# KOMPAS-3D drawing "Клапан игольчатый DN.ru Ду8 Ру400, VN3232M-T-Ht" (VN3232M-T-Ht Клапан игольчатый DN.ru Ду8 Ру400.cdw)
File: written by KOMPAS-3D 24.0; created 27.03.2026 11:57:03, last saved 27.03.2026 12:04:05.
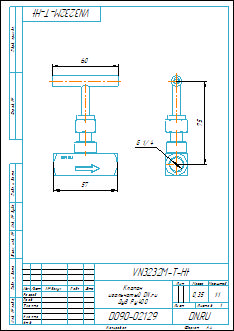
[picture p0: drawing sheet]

Document properties: Автор: Илья; Форматы листов документа: A4; Полное имя файла: VN3232M-T-Ht Клапан игольчатый DN.ru Ду8 Ру400.m3d; Масса: 0.35; Наименование: Клапан игольчатый DN.ru Ду8 Ру400; Количество листов документа: 1; Примечание: D090-02129

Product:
- Body: Body3  | qty 1
    Масса: 0.248386
- Part/product: Клапан игольчатый DN.ru Ду8 Ру400  | designation VN3232M-T-Ht
    Масса: 0.35
    Раздел спецификации: Прочие изделия
    Форматы листов документа: A4
    Примечание: D090-02129

Views: Проекционный вид 2
Referenced files in D:\Обмен\Заказы с фриланса\DN.ru\VNxxM-T-Ht Клапан игольчатый DN.ru Ду8-50 Ру400\VN3232M-T-Ht Клапан игольчатый DN.ru Ду8-50 Ру400\DN8\: VN3232M-T-Ht Клапан игольчатый DN.ru Ду8 Ру400.m3d, VN3232M-T-Ht Клапан игольчатый DN.ru Ду8 Ру400.cdw
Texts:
  VN3232M-T-Ht
  Клапан
  игольчатый DN.ru
  Ду8 Ру400
  Body3
  Клапан игольчатый DN.ru Ду8 Ру400
  VN3232M-T-Ht Клапан игольчатый DN.ru Ду8 Ру400
Dimensions and other numbers on the sheet: 0; 3; 4; 75; 1:1; 1; 2; 0,35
